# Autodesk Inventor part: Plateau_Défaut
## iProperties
Shininess: 64.0
Length Units: 11269
Angle Units: 11279
Time Units: 11290
Mass Units: 11283
Length Display Precision: 3
Angle Display Precision: 2
Compacted: True
Part Number: Plateau_Défaut
Document SubType Name: Modeling
Created: 2006-11
Material: Par défaut
Designer: profs_sti
Density: 0.0
Volumn: 0.0
Area: 0.0
PropertySet Name: Model Information
Control State: 0
Master: False
Checked Out: False
Author: profs_sti
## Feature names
1. Base1
